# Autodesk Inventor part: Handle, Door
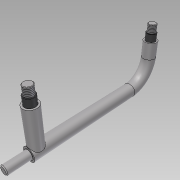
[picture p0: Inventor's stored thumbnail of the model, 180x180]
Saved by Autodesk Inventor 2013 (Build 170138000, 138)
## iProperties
Created: 2012-10
Part Number: Handle, Door
Material: Stainless Steel
Document SubType Name: Modeling
Designer: VMuser
Density: 8.08 g/cm^3
Mass: 224.153 g
Surface Area: 238.952 cm^2
Volume: 27.7417 cm^3
Author: VMuser
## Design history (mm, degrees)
derived "handle on the glass-2.iam"
delete_face "Delete Face1"
delete_face "Delete Face2"
delete_face "Delete Face3"
feature "Move Face1"
sketch "Sketch1"
  geometry: C1 r 8 at (0, 0) reference; C2 r 5 at (0, 0); C3 r 6 at (0, 0)
  constraints: 2 centre point, 2 coincident
  dimensions: "d1" = 10 diameter of C2; "d4" = 12 diameter of C3
extrude "Extrusion1" join sketch "Sketch1" distance "d2" = 19; taper "d3" = 0 deg
extrude "Extrusion2" join sketch "Sketch1" distance "d5" = 9; taper "d6" = 0 deg
sketch "Sketch2"
  geometry: C1 r 8 at (0, 0); C2 r 5 at (0, 0); C3 r 6 at (0, 0)
  constraints: 3 centre point, 2 coincident
  dimensions: "d8" = 10 diameter of C2 (= d1); "d7" = 12 diameter of C3 (= d4)
extrude "Extrusion3" join sketch "Sketch2" taper "d10" = 0 deg (computed from d3); distance "d11" = 19 (= d2)
extrude "Extrusion4" join sketch "Sketch2" taper "d13" = 0 deg (computed from d6); distance "d14" = 9 (= d5)
chamfer "Chamfer1" distance "d19" = 0.5; stored, may be unused: second distance "d20" = 2, angle "d21" = 45 deg
thread "Thread1" dims "d15" = 10, "d16" = 0
thread "Thread2" dims "d17" = 10, "d18" = 0
body "Solid1"
node "handle on the glass-2.ipt:1" dims "d0" = 10
node "clamp.ipt:1" dims "d0" = 10
node "support for a new pen.ipt:1" dims "d0" = 10
node "stand.ipt:1" dims "d0" = 10
node "support for a new pen.ipt:2" dims "d0" = 10
